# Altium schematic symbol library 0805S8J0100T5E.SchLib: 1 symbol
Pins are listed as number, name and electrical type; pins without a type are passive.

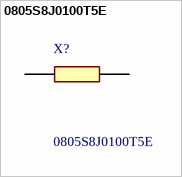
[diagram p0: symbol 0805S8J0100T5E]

## 0805S8J0100T5E
designator X?
THICK FILM CHIP RESISTORS; Manufacturer_Name: ROYALOHM; Geometry.Height: 0.65mm
footprint RESC2013X65N
pins: 1, 2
